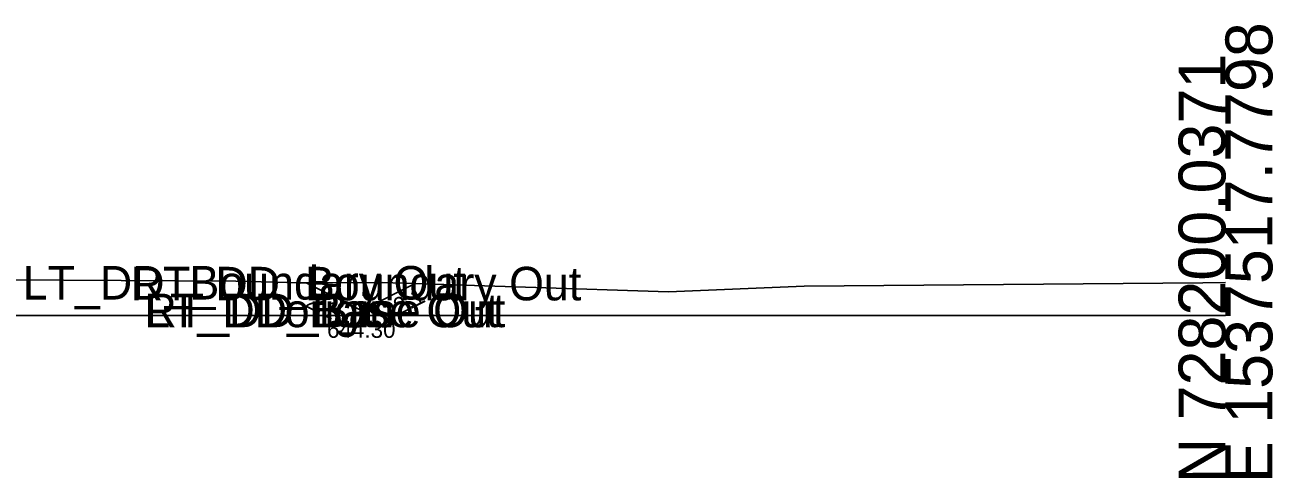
# Model space of a CAD drawing. Extents: x -26 to 1203, y -10 to 9522.
# Drawn here: x 128.3 to 202.8, y 6490.3 to 6517.3 of the extents above; entities that cross this region are included whole.
import ezdxf

# ---------------------------------------------------------------- set-up
doc = ezdxf.new("R2010")
doc.units = 0
for name, color, linetype in [('Exist Cross Section Cell', 7, 'Continuous'), ('Exist XS Ground Line', 7, 'Continuous'), ('Old_Level_63', 7, 'Continuous'), ('Prop CMT Ditch DDE', 7, 'Continuous'), ('Prop XS Ditch Slope Text', 7, 'Continuous'), ('Prop XS Ditch Standard Text', 7, 'Continuous')]:
    doc.layers.add(name, color=color, linetype=linetype)

msp = doc.modelspace()

# ---------------------------------------------------------------- linework, layer by layer
at = {"layer": 'Exist Cross Section Cell'}
msp.add_line((100, 6500), (200, 6500), dxfattribs=at)
at = {"layer": 'Exist XS Ground Line'}
msp.add_lwpolyline([(59.657, 6501.797), (78.767, 6501.94), (79.052, 6501.945), (86.254, 6501.932), (100, 6501.908), (101.064, 6501.906), (113.653, 6501.843), (114.263, 6501.897), (117.13, 6502.278), (120.323, 6502.168), (140.892, 6502.05), (144.702, 6501.951), (146.679, 6501.947), (149.652, 6501.962), (166.742, 6501.413), (174.841, 6501.756), (198.65, 6501.946), (200, 6501.956)], dxfattribs=at)
at = {"layer": 'Prop CMT Ditch DDE'}
for points in [[(148.4, 6500.3), (145.1, 6501.95)], [(148.4, 6500.3), (151.6, 6501.9)], [(148.4, 6500.3), (148.4, 6500.3)]]:
    msp.add_lwpolyline(points, dxfattribs=at)

# ---------------------------------------------------------------- texts
at = {"layer": 'Exist Cross Section Cell'}
for s, p in [('E 1537517.7798', (202.8, 6490)), ('N 728200.0371', (200, 6490))]:
    msp.add_text(s, height=2.8, rotation=90, dxfattribs=at).set_placement(p)
at = {"layer": 'Old_Level_63'}
for s, p in [('LT_DD_Boundary Out', (128.171, 6500.95)), ('RT_DD_Boundary Out', (134.623, 6500.9)), ('RT_DD_Base Out', (135.439, 6499.3)), ('LT_DD_Base Out', (135.487, 6499.3)), ('origin', (143.817, 6499.3))]:
    msp.add_text(s, height=2, dxfattribs=at).set_placement(p)
at = {"layer": 'Prop XS Ditch Slope Text'}
for rotation, p in [(26.56505, (150.628, 6500.012)), (333.43495, (144.982, 6500.548))]:
    msp.add_text('2:1', height=1, rotation=rotation, dxfattribs=at).set_placement(p)
at = {"layer": 'Prop XS Ditch Standard Text'}
msp.add_text('644.30', height=1, dxfattribs=at).set_placement((146.345, 6498.667))

doc.saveas('drawing.dxf')
